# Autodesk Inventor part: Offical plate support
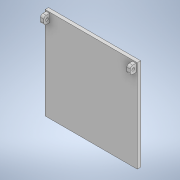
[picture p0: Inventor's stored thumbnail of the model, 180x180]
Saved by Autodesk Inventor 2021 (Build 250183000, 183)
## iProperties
Created: 2021-02
Part Number: Offical plate support
Material: Generic
Document SubType Name: Modeling
Designer: Owner
Density: 1 g/cm^3
Appearance: Default
Author: Owner
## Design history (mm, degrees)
sketch "Sketch1"
  geometry: L1 (23.914, 0)-(103.914, 0); L2 (103.914, 0)-(103.914, -80); L3 (103.914, -80)-(23.914, -80); L4 (23.914, -80)-(23.914, 0); 1 further point
  constraints: 8 end point, 2 parallel, 1 horizontal, 1 perpendicular
  dimensions: "d0" = 80 distance of L1.start L1.end; "d1" = 80 distance of L1.end L2.end
extrude "Extrusion1" new body sketch "Sketch1" distance "d2" = 3; taper "d3" = 0 deg
sketch "Sketch2"
  geometry: L1 (23.914, 0)-(23.914, -80) reference; L2 (24.914, -0.806)-(27.914, -0.806); L3 (27.914, -0.806)-(27.914, -7.806); L4 (27.914, -7.806)-(24.914, -7.806); L5 (24.914, -7.806)-(24.914, -0.806); L6 (103.914, -80)-(103.914, 0) reference; L7 (102.914, -0.806)-(99.914, -0.806); L8 (99.914, -0.806)-(99.914, -7.806); L9 (99.914, -7.806)-(102.914, -7.806); L10 (102.914, -7.806)-(102.914, -0.806); 1 further point
  constraints: 16 end point, 4 parallel, 2 horizontal, 2 perpendicular
  dimensions: "d5" = 3 distance of L3.end L4.end; "d6" = 7 distance of L2.end L3.end; "d8" = 3 distance of L8.end L9.end; "d9" = 1 distance between parallel lines of L6 L10
extrude "Extrusion2" join sketch "Sketch2" distance "d10" = 5; taper "d11" = 0 deg
sketch "Sketch3"
  geometry: 2 further points
hole "Hole1" sketch "Sketch3" at (-2.391, 3.529) diameter "d12" = 2.5; stored, may be unused: countersink angle "d16" = 90 deg, drill point angle "d18" = 118 deg; dims "d13" = 6, "d14" = 4, "d15" = 2, "d17" = 8
fillet "Fillet1" dims "d19" = 2
body "Solid1"
